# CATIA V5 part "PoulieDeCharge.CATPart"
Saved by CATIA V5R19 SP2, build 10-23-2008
Part number: Poulie
Bounding box of the stored display mesh (mm): x -70 to 18, y -30 to 30, z -30 to 30
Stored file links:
  D:\SCHOOL\FRANCE\BANC_POUTRE_EN_MOUSSE\PoulieDeCharge.CATPart
  C:\Program Files\Dassault Systemes\B19\intel_a\reffiles\standard\MetricThickPitch.txt
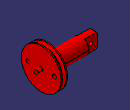
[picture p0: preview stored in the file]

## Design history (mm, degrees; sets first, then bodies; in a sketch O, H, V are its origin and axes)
AxisSystem1: origin (0, 0, 0), X (1, 0, 0), Y (0, 1, 0), Z (0, 0, 1)
Body1 (main body)
  Sketch1 on yz-plane, origin (0, 0, 0), H (0, 1, 0), V (0, 0, 1)
    circle A1 centre (0, 0) radius 30
    radius A1 = 30
  Pad1: profile Sketch1, direction (1, 0, 0), length 10
  Sketch2 on end face of Pad1, origin (10, 0, 0), H (0, 1, 0), V (0, 0, 1)
    circle A1 centre (0, 0) radius 3
    radius A1 = 3
  Pad2: profile Sketch2, direction (1, 0, 0), length 8
  Sketch3 on start face of Pad1, origin (0, 0, 0), H (0, -1, 0), V (0, 0, 1)
    circle A1 centre (0, 0) radius 14
    radius A1 = 14
  Pad3: profile Sketch3, direction (-1, 0, 0), length 10
  Sketch4 on end face of Pad3, origin (-10, 0, 0), H (0, -1, 0), V (0, 0, 1)
    circle A1 centre (0, 0) radius 12
    radius A1 = 12
  Pad4: profile Sketch4, direction (-1, 0, 0), length 60
  Chamfer1: length 2, angle 45, on edge [face of Pad4 from Sketch4.A1 | end face of Pad4]
  Sketch5 on end face of Pad1, origin (10, 0, 0), H (0, 1, 0), V (0, 0, 1)
    point P1 (20, 0)
    axis line L1 (-22.395, 0) -> (45.7979, 0)
    reference projected point E1 (0, 0) from vertex [YZ plane of AxisSystem1 | ZX plane of AxisSystem1 | XY plane of AxisSystem1]
    distance P1 E1 = 20
    coincidence: L1 O, P1 L1
    horizontal: L1 H
  Hole1: placed by Sketch5, at (10, 20, 0) direction (-1, 0, 0), diameter 6, through (limit type 3)
  RectPattern1: of Hole1, direction 1 instances 2, spacing 40, along edge [YZ plane of AxisSystem1 | XY plane of AxisSystem1] reversed
  Sketch6 on ZX plane of AxisSystem1, origin (0, 0, 0), H (0, 0, 1), V (1, 0, 0)
    point P1 (33, 9)
    line L1 (33, 9) -> (25, 6.5)
    point P2 (25, 6.5)
    line L2 (25, 6.5) -> (25, 3.5)
    point P3 (25, 3.5)
    line L3 (25, 3.5) -> (33, 1)
    point P4 (33, 1)
    line L4 (33, 1) -> (33, 9)
    axis line L5 (-7.5428, 5) -> (51.6025, 5)
    distance H L5 = 5
    length L2 = 3
    length L4 = 8
    distance L4 L2 = 8
    distance V L2 = 25
    vertical: L2 V, L4 V
    horizontal: L5 H
    symmetry: P2 P3 L5, P1 P4 L5
  Groove1: profile Sketch6, axis axis of face of Pad2 from Sketch2.A1, angle 360
  Sketch7 on {plane type Tangent, Support face of Groove1 from Sketch6.L2, RefPoint {point type OnSurface, Support face of Groove1 from Sketch6.L2, RefPoint {point stored without definition}, Length 0, Direction (0, 847.0429, 531.5246)}}, origin (4.9493, -13.2881, 21.1761), H (1, 0, 0), V (0, 0.847, 0.5315)
    point P1 (0, 0)
  Hole2: placed by Sketch7, at (4.9493, -13.2881, 21.1761) direction (0, 0.5315, -0.847), diameter 2.459, depth 5, threaded "M3", thread diameter 3, thread depth 5, pitch 0.5
  Sketch8 on end face of Pad4, origin (-70, 0, 0), H (0, -1, 0), V (0, 0, 1)
    projected circle E1 centre (0, 0) radius 12 from edge [face of Pad4 from Sketch4.A1 | face of Chamfer1]
    projected arc E2 centre (0, 0) radius 12 from (5, -10.9087) to (5, 10.9087) ccw from edge [face of Pad4 from Sketch4.A1 | face of Chamfer1]
    projected arc E3 centre (0, 0) radius 12 from (-5, 10.9087) to (-5, -10.9087) ccw from edge [face of Pad4 from Sketch4.A1 | face of Chamfer1]
    line L1 (5, 10.9087) -> (5, -10.9087)
    line L2 (-5, 10.9087) -> (-5, -10.9087)
    axis line L3 (0, 26.2288) -> (0, -34.6791)
    point P1 (0, 26.2288)
    point P3 (5, 10.9087)
    point P4 (-5, 10.9087)
    point P5 (5, -10.9087)
    point P6 (-5, -10.9087)
    distance L2 L1 = 10
    vertical: L1 V, L2 V
    coincidence: P1 V, V L3, E1 P3, E1 P4, E1 P5, E1 P6
    symmetry: L1 L2 L3
  Pocket1: profile Sketch8, direction (1, 0, 0), length 20
  Sketch9 on face of Pocket1 from Sketch8.L1, origin (-60.3461, -5, -0.7856), H (1, 0, 0), V (0, 0, 1)
    point P1 (0.3461, 0.7856)
    reference projected line E1 (-9.6539, 9.4459) -> (-9.6539, -7.8746) from edge [end face of Pad4 | face of Pocket1 from Sketch8.L1]
    reference intersected line E2 through (0, 0.7856) direction (-1, 0) from xy-plane
    distance E1 P1 = 10
    coincidence: P1 E2
  Hole3: placed by Sketch9, at (-60, -5, 0) direction (0, 1, 0), diameter 6, through (limit type 6)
